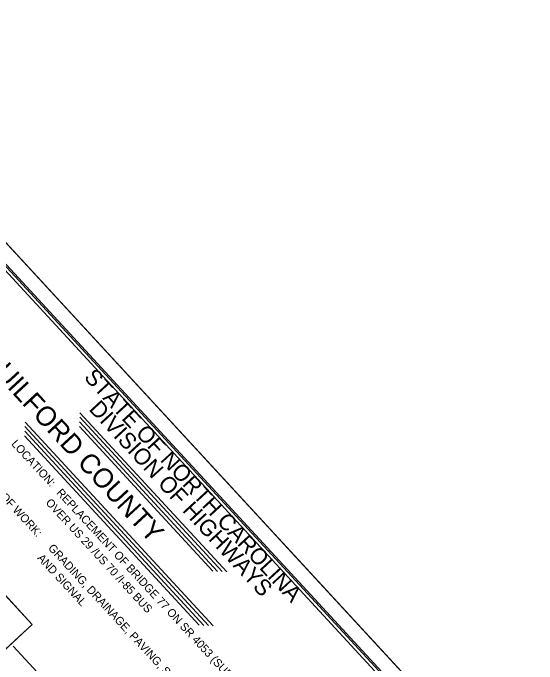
# Model space of a CAD drawing. Extents: x 1695041 to 1706254, y 786537 to 798223.
# Drawn here: x 1703837 to 1706254, y 795222 to 798223 of the extents above; entities that cross this region are included whole.
import ezdxf

# ---------------------------------------------------------------- set-up
doc = ezdxf.new("R2010")
doc.units = 0
for name, color, linetype in [('Default', 7, 'Continuous'), ('Sheet Cutting Line CELL', 7, 'Continuous'), ('Sheet Data Field CELL', 7, 'Continuous'), ('Sheet Plot Border Inside CELL', 7, 'Continuous'), ('Sheet Plot Border Outside CELL', 7, 'Continuous'), ('Sheet Title CELL', 7, 'Continuous'), ('Sheet Title Data Points CELL', 7, 'Continuous')]:
    doc.layers.add(name, color=color, linetype=linetype)

msp = doc.modelspace()

# ---------------------------------------------------------------- linework, layer by layer
at = {"layer": 'Default'}
for points in [[(1702347.2, 796012.7), (1702159.6, 795839.5), (1703188.6, 794724.8), (1703925.1, 795404.6), (1702896.1, 796519.3), (1702395.5, 796057.2)], [(1704247.3, 793859.6), (1704746.6, 794320.4), (1703838.4, 795304.4)]]:
    msp.add_lwpolyline(points, dxfattribs=at)
msp.add_lwpolyline([(1703925.1, 795404.6), (1703732.6, 795613), (1703574.9, 795467.4), (1703767.3, 795259)], close=True, dxfattribs=at)
at = {"layer": 'Sheet Cutting Line CELL'}
msp.add_line((1702826.9, 798222.8), (1706253.6, 794510.5), dxfattribs=at)
at = {"layer": 'Sheet Plot Border Inside CELL'}
msp.add_lwpolyline([(1700478, 796001.5), (1703869.1, 792327.8), (1706194.9, 794474.8), (1702803.9, 798148.4)], close=True, dxfattribs=at)
at = {"layer": 'Sheet Plot Border Outside CELL'}
msp.add_lwpolyline([(1706253.6, 794510.5), (1702826.9, 798222.8), (1700402.1, 795984.5), (1703828.7, 792272.3)], close=True, dxfattribs=at)
at = {"layer": 'Sheet Title CELL'}
for p, q in [((1704145.6, 796380.4), (1704822.7, 795646.9)), ((1704144.8, 796359.3), (1704801.5, 795647.8)), ((1703892, 796316.4), (1704738.5, 795399.3)), ((1703892.9, 796337.6), (1704759.7, 795398.5)), ((1704143.1, 796316.8), (1704759.1, 795649.5)), ((1704143.9, 796338), (1704780.3, 795648.6)), ((1703891.2, 796295.2), (1704717.3, 795400.2)), ((1703890.3, 796274), (1704696.1, 795401))]:
    msp.add_line(p, q, dxfattribs=at)
for points in [[(1706143.6, 794519.2), (1703132, 797781.8)], [(1706122.3, 794520), (1703232.9, 797650.3)]]:
    msp.add_lwpolyline(points, dxfattribs=at)
at = {"layer": 'Sheet Title Data Points CELL'}
for p, q in [((1704362.3, 795895), (1704362.3, 795895)), ((1704486.7, 795519.7), (1704486.7, 795519.7))]:
    msp.add_line(p, q, dxfattribs=at)

# ---------------------------------------------------------------- texts
at = {"layer": 'Sheet Data Field CELL'}
for s, height, p in [('       GUILFORD COUNTY       ', 90, (1703526.2, 796800.7)), ('REPLACEMENT OF BRIDGE 77 ON SR 4053 (SURRETT DR)', 37.5, (1704034.8, 796009.4)), ('OVER US 29 /US 70 /I-85 BUS             ', 37.5, (1703985.2, 795963.6)), ('GRADING, DRAINAGE, PAVING, STRUCTURE    ', 37.5, (1703996.4, 795754.4)), ('AND SIGNAL                              ', 37.5, (1703946.8, 795708.6))]:
    msp.add_text(s, height=height, rotation=312.7091, dxfattribs=at).set_placement(p)
at = {"layer": 'Sheet Title CELL'}
for s, height, p in [('STATE OF NORTH CAROLINA', 75, (1704160.8, 796540.6)), ('DIVISION OF HIGHWAYS', 75, (1704183.5, 796394.6)), ('LOCATION: ', 37.5, (1703826.7, 796234.8)), ('TYPE OF WORK:', 37.5, (1703677.8, 796097.5))]:
    msp.add_text(s, height=height, rotation=312.7091, dxfattribs=at).set_placement(p)

doc.saveas('drawing.dxf')
